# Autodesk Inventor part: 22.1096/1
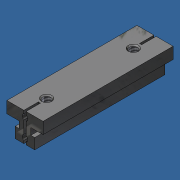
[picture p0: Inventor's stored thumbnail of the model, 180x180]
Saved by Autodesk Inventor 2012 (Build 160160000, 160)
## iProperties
Created: 2007-06
Part Number: 22.1096/1
Material: UHMW, Black
Document SubType Name: Modeling
Designer: Andy Moles
Density: 0.94 g/cm^3
Mass: 27.0867 g
Surface Area: 110.301 cm^2
Volume: 28.8156 cm^3
Description: L = 3.54", MACHINE TO 22.1096/1
Stock Number: 22.1088 SLIDE BAR 8
Author: Andy Moles
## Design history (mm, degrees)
sketch "Sketch1"
  geometry: L1 (4.1, 0)-(4.1, -4.6); L2 (12.5, 0)-(4.1, 0); L3 (12.5, 8)-(12.5, 0); L4 (-12.5, 8)-(12.5, 8); L5 (-12.5, 0)-(-12.5, 8); L6 (-4.1, 0)-(-12.5, 0); L7 (-4.1, -4.6)-(-4.1, 0); L8 (-6.75, -4.6)-(-4.1, -4.6); L9 (-6.75, -12)-(-6.75, -4.6); L10 (6.75, -12)-(-6.75, -12); L11 (6.75, -4.6)-(6.75, -12); L12 (4.1, -4.6)-(6.75, -4.6); 2 further points
  constraints: 24 end point
extrude "Extrusion1" new body sketch "Sketch1" stored distance "d0" = 90; taper "d1" = 0 deg
sketch "Sketch2"
  geometry: L1 (-12.5, 8)-(12.5, 8) reference; L2 (-12.5, 0)-(-12.5, 8) reference; L3 (-6.75, -12)-(-6.75, -4.6) reference; L4 (6.75, -12)-(-6.75, -12) reference; L5 (6.75, -4.6)-(6.75, -12) reference; L6 (-0.75, 8)-(0.75, 8); L7 (-0.75, -12)-(0.75, -12); L8 (-0.75, 5.854)-(-0.75, 8); L9 (0.75, 5.854)-(0.75, 8); L10 (-0.75, -12)-(-0.75, -10.154); L11 (-0.75, -6.446)-(-0.75, 2.146); L12 (0.75, -12)-(0.75, -10.154); L13 (0.75, -6.446)-(0.75, 2.146); A1 r 2 centre (0, 4) between (-0.75, 5.854) and (-0.75, 2.146); A2 r 2 centre (0, 4) between (0.75, 2.146) and (0.75, 5.854); A3 r 2 centre (0, -8.3) between (-0.75, -6.446) and (-0.75, -10.154); A4 r 2 centre (0, -8.3) between (0.75, -10.154) and (0.75, -6.446); 6 further points
  constraints: 16 end point, 8 point on circle, 6 perpendicular, 5 midpoint, 4 centre point, 4 parallel, 4 point on line, 3 vertical alignment, 2 horizontal alignment
extrude "Extrusion2" cut sketch "Sketch2" distance "d5" = 10; taper "d6" = 0 deg
sketch "Sketch3"
  geometry: C1 r 2.8 at (12.5, -75); 1 further point
  constraints: 1 centre point, 1 vertical alignment
  dimensions: "d7" = 5.6 diameter of C1; "d8" = 30 distance of C1.centre point (12.5, -45)
extrude "Extrusion3" cut sketch "Sketch3" distance "d9" = 14; taper "d10" = 0 deg
thread "Thread1" dims "d11" = 10, "d12" = 0
thread "Thread2" dims "d13" = 10, "d14" = 0
thread "Thread3" dims "d15" = 10, "d16" = 0
thread "Thread4" dims "d17" = 10, "d18" = 0
mirror "Mirror1"
chamfer "Chamfer2" distance "d26" = 0.79375; stored, may be unused: second distance "d27" = 2, angle "d28" = 45 deg
body "Solid1"
other parameters: "d2" = 4, "d3" = 1.5, "d4" = 4
